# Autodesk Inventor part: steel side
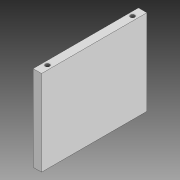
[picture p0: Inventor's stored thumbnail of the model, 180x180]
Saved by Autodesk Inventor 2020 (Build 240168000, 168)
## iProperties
Created: 2019-12
Part Number: steel side
Material: Generic
Document SubType Name: Modeling
Designer: MPI
Density: 1 g/cm^3
Appearance: Default
Author: MPI
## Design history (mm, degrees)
sketch "Sketch1"
  geometry: L1 (-6.35, 64.389)-(6.35, 64.389); L2 (6.35, 64.389)-(6.35, -64.389); L3 (6.35, -64.389)-(-6.35, -64.389); L4 (-6.35, -64.389)-(-6.35, 64.389); L5 (6.35, 64.389)-(-6.35, -64.389); L6 (-6.35, 64.389)-(6.35, -64.389); 2 further points
  constraints: 12 end point, 2 parallel, 1 coincident, 1 horizontal, 1 midpoint, 1 perpendicular
  dimensions: "d0" = 128.778 distance of L1.end L2.end; "d1" = 12.7 distance of L1.start L1.end
extrude "Extrusion1" new body sketch "Sketch1" distance "d2" = 158.75; taper "d3" = 0 deg
sketch "Sketch2"
  geometry: L1 (0, 0)-(0, -158.75) reference; L2 (12.7, -158.75)-(0, -158.75) reference; 3 further points
  dimensions: "d11" = 6.35 distance from line of L1 point (6.35, -15.24); "d12" = 6.35 distance from line of L1 point (6.35, -143.51); "d13" = 15.24 distance from line of point (6.35, -143.51) L2; "d14" = 15.24 distance of point (6.35, 0) point (6.35, -15.24)
hole "Hole1" sketch "Sketch2" at (6.35, -143.51), (6.35, -15.24) diameter "d4" = 6.4008; stored, may be unused: countersink angle "d8" = 82 deg, drill point angle "d10" = 118 deg; dims "d5" = 22.86, "d6" = 16.129, "d7" = 0.508, "d9" = 22.9362
mirror "Mirror1"
body "Solid1"
